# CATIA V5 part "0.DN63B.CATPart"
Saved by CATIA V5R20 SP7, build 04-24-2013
Part number: 0.DN63B
Material "Nessuno"
Bounding box of the stored display mesh (mm): x -14.589 to 149.213, y -143.683 to 0, z -56.919 to 41.584
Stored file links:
  C:\Users\designer2\Desktop\Ottobre 2022\25-10-2022\04\Yori Evo 48V\0.DN63B.CATPart
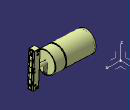
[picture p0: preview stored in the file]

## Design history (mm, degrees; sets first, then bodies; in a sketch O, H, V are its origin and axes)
AxisSystem1: origin (0, 0, 0), X (1, 0, 0), Y (0, 1, 0), Z (0, 0, 1)
Set1
  DatumSurface1
Body1 (main body), material "Nessuno"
